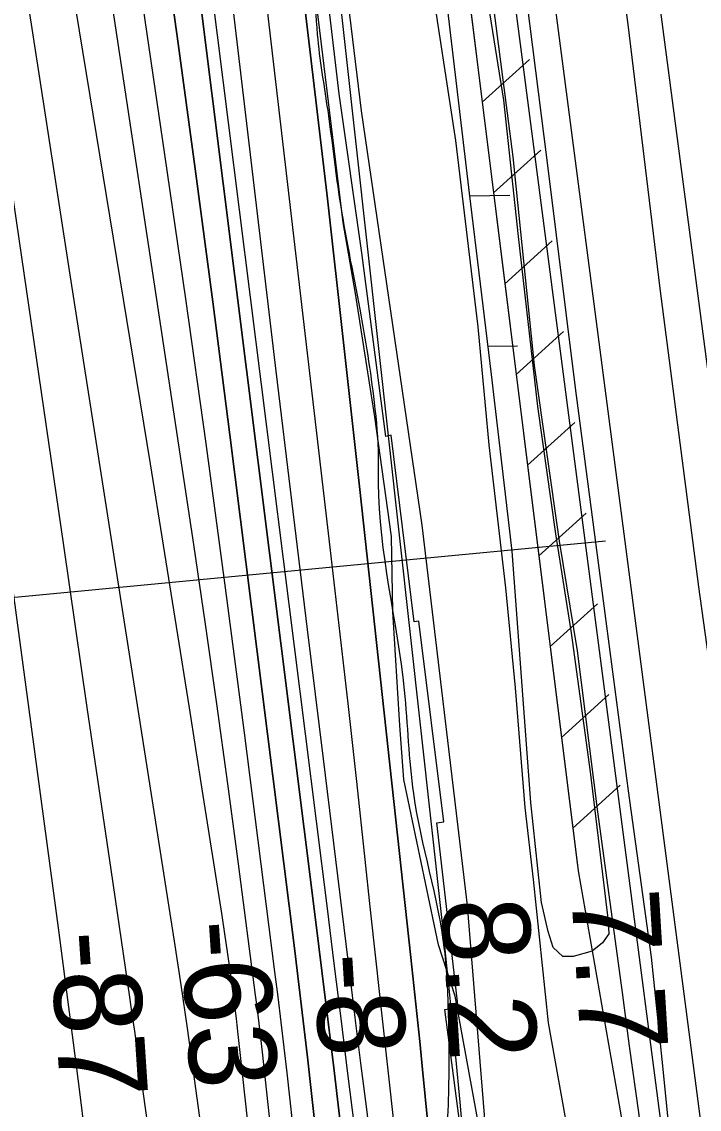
# Model space of a CAD drawing. Extents: x 3694830 to 3732949, y 415201 to 440970.
# Drawn here: x 3718315 to 3718833, y 425246 to 426079 of the extents above; entities that cross this region are included whole.
import ezdxf

# ---------------------------------------------------------------- set-up
doc = ezdxf.new("R2010")
doc.units = 0
for name, color, linetype in [('V-FLOD-BASE', 7, 'Continuous'), ('V-LEVE-TOET', 7, 'Continuous'), ('V-RIVR-EDGE', 7, 'Continuous'), ('V-RIVR-RANG', 7, 'Continuous'), ('V-ROAD-CNTR', 7, 'Continuous'), ('V-RRAP-FSHR', 7, 'Continuous'), ('V-RRAP-RVMT', 7, 'Continuous'), ('V-SITE-VEGE', 7, 'Continuous'), ('V-SURV-LINE', 7, 'Continuous'), ('V-TOPO-DPTH', 7, 'Continuous'), ('V-TOPO-MAJR', 7, 'Continuous'), ('V-TOPO-MINR', 7, 'Continuous'), ('V-TOPO-WATR', 7, 'Continuous'), ('V-WETL-SWMP', 7, 'Continuous')]:
    doc.layers.add(name, color=color, linetype=linetype)

msp = doc.modelspace()

# ---------------------------------------------------------------- linework, layer by layer
at = {"layer": 'V-FLOD-BASE'}
msp.add_lwpolyline([(3718858.85, 424393.11), (3718851.68, 424539.09), (3718851.69, 424574.68), (3718851.71, 424624.71), (3718850.69, 424666.49), (3718849.15, 424680.42), (3718844, 424708.79), (3718844, 424717.56), (3718844.52, 424728.39), (3718840.95, 424830.01), (3718832.23, 424964.64), (3718827.62, 425062.12), (3718824.03, 425114.74), (3718816.82, 425167.35), (3718805, 425284.45), (3718796.77, 425362.85), (3718779.28, 425490.26), (3718761.28, 425625.92), (3718738.64, 425798.73), (3718717.04, 425973.08), (3718690.81, 426180.44)], dxfattribs=at)
at = {"layer": 'V-LEVE-TOET'}
for points in [[(3718899.96, 425078.36), (3718901.03, 425108.14), (3718896.79, 425132.59), (3718888.31, 425204.91), (3718875.59, 425321.88), (3718855.44, 425484.58), (3718833.17, 425646.21), (3718803.47, 425874.84), (3718779.09, 426076.89), (3718752.57, 426276.81), (3718727.12, 426479.91), (3718690, 426734.07), (3718666.66, 426904.21), (3718647.58, 427073.29), (3718635.92, 427156.23), (3718626.37, 427242.37), (3718612.59, 427357.22), (3718587.13, 427524.17), (3718573.35, 427643.27)], [(3718826.56, 424506.85), (3718825.53, 424612.66), (3718820.27, 424766.31), (3718810.22, 424932.73), (3718799.13, 425134.77), (3718791.7, 425193.25), (3718787.47, 425242.17), (3718780.04, 425294.81), (3718774.74, 425335.75), (3718755.65, 425473.99), (3718740.27, 425597.34), (3718726.48, 425681.35), (3718707.39, 425815.87), (3718690.96, 425975.38), (3718667.63, 426154.56)]]:
    msp.add_lwpolyline(points, dxfattribs=at)
at = {"layer": 'V-RIVR-EDGE'}
msp.add_spline([(3716285.15, 433216.71), (3716310.38, 433178.21), (3716330.2, 433149.68), (3716351.38, 433122.49), (3716380.66, 433076.75), (3716399.14, 433050.48), (3716447.79, 432976.21), (3716475.25, 432930.47), (3716501.83, 432891.07), (3716527.51, 432851.22), (3716586.04, 432749.34), (3716608.1, 432711.75), (3716608.09, 432707.68), (3716608.07, 432700.45), (3716613.02, 432690.94), (3716627.43, 432664.23), (3716633.27, 432651.55), (3716643.19, 432639.32), (3716675.17, 432589.5), (3716706.24, 432538.33), (3716726.94, 432498.04), (3716741.33, 432463.64), (3716748.51, 432442.82), (3716788.59, 432378.52), (3716817.43, 432339.56), (3716842.2, 432297.45), (3716889.46, 432209.61), (3716920.5, 432144.42), (3716938.04, 432109.56), (3716956.5, 432075.15), (3716988.92, 432022.62), (3717009.18, 431986.85), (3717026.3, 431960.13), (3717062.32, 431897.65), (3717093.37, 431840.15), (3717112.26, 431799.86), (3717149.12, 431711.14), (3717176.54, 431644.61), (3717201.25, 431580.79), (3717210.68, 431556.35), (3717248.47, 431478.94), (3717267.81, 431435.48), (3717289.41, 431392.93), (3717306.48, 431346.77), (3717328.07, 431301.04), (3717339.31, 431276.6), (3717352.34, 431244.01), (3717362.7, 431226.35), (3717376.21, 431205.52), (3717389.26, 431178.36), (3717401.37, 431141.7), (3717407.18, 431113.2), (3717409.87, 431101.89), (3717419.75, 431075.64), (3717452.49, 430968.85), (3717469.09, 430916.81), (3717483.44, 430865.23), (3717505.45, 430810.01), (3717526.57, 430753.44), (3717540.49, 430715.43), (3717579.07, 430593.25), (3717599.25, 430526.28), (3717616.31, 430474.69), (3717628.88, 430437.13), (3717638.74, 430405), (3717647.69, 430364.28), (3717653.48, 430331.72), (3717658.42, 430314.52), (3717667.85, 430290.08), (3717679.53, 430260.66), (3717690.34, 430242.1), (3717695.71, 430221.28), (3717698.37, 430200.03), (3717697.85, 430171.99), (3717701.42, 430152.99), (3717705.91, 430140.77), (3717716.26, 430119.95), (3717727.97, 430100.48), (3717735.6, 430076.49), (3717737.82, 430059.31), (3717749.05, 430029.89), (3717760.76, 430011.77), (3717771.56, 429990.04), (3717776.48, 429968.33), (3717783.19, 429941.63), (3717791.73, 429917.65), (3717803.43, 429898.63), (3717812.42, 429876.45), (3717819.16, 429857.44), (3717834.88, 429816.71), (3717846.52, 429770.11), (3717854.12, 429734.82), (3717863.55, 429706.31), (3717878.83, 429667.39), (3717891.37, 429622.59), (3717903.49, 429586.39), (3717917.82, 429530.29), (3717931.71, 429476.45), (3717959.46, 429363.79), (3717976.51, 429307.23), (3717987.25, 429262.44), (3718014.11, 429153.85), (3718027.51, 429090.07), (3718040.47, 429028.09), (3718052.52, 428962.5), (3718057.84, 428919.98), (3718056.9, 428903.25), (3718056.86, 428887.88), (3718057.71, 428868.43), (3718061.29, 428850.79), (3718065.77, 428833.6), (3718082.36, 428779.3), (3718091.33, 428748.08), (3718100.28, 428710.98), (3718111.45, 428657.14), (3718116.36, 428631.81), (3718128.31, 428525.97), (3718136.77, 428473.05), (3718141.66, 428440.03), (3718152.32, 428360.88), (3718163.9, 428291.22), (3718171.05, 428256.38), (3718178.23, 428236.47), (3718193.92, 428178.55), (3718199.74, 428157.29), (3718197.91, 428150.06), (3718196.52, 428133.33), (3718197.39, 428121.12), (3718204.12, 428098.04), (3718215.36, 428075.41), (3718227.96, 428049.6), (3718240.08, 428011.59), (3718242.71, 427978.58), (3718251.11, 427901.24), (3718254.15, 427852.85), (3718257.69, 427822.1), (3718271.5, 427736.15), (3718281.74, 427671.92), (3718287.91, 427606.34), (3718295.91, 427551.61), (3718303.87, 427477.44), (3718310.12, 427447.13), (3718323.14, 427407.76), (3718345.15, 427350.28), (3718351.41, 427321.78), (3718363.48, 427267.49), (3718378.28, 427217.26), (3718397.99, 427141.25), (3718402.87, 427105.52), (3718405.92, 427056.68), (3718404.86, 426993.38), (3718419.58, 426915.12), (3718427.13, 426857.67), (3718428.77, 426789.85), (3718439.53, 426753.19), (3718453.89, 426709.75), (3718458.33, 426677.18), (3718461.82, 426625.18), (3718465.34, 426583.57), (3718482.71, 426479.53), (3718492.52, 426423.89), (3718501, 426378.2), (3718502.74, 426350.16), (3718512.91, 426256.09), (3718518.23, 426213.12), (3718524.03, 426182.81), (3718533.44, 426148.88), (3718540.93, 426069.28), (3718548.93, 426010.93), (3718557.81, 425944.44), (3718573.42, 425858.94), (3718584.55, 425787.48), (3718587.61, 425745.42), (3718587.56, 425725.97), (3718607.51, 425567.22), (3718614.55, 425488.07), (3718638.22, 425368.64), (3718641.26, 425318.45), (3718641.09, 425249.72), (3718640.1, 425214), (3718649.84, 425130.78), (3718658.73, 425069.26), (3718661.82, 425037.15), (3718660.41, 425016.36), (3718674.96, 424864.4), (3718675.73, 424812.85), (3718692.62, 424694.79), (3718696.05, 424618.82), (3718696.4, 424575.87), (3718706.12, 424484.51), (3718711.87, 424431.59), (3718715.41, 424403.09), (3718735.93, 424289.1), (3718746.6, 424215.37), (3718759.9, 424108.63), (3718772.36, 424027.21), (3718777.72, 423998.26), (3718795.91, 423858.04), (3718805.72, 423804.21), (3718812.44, 423776.61), (3718829, 423707.39), (3718835.67, 423662.61), (3718835.09, 423611.97), (3718835, 423576.7), (3718839.35, 423505.25), (3718842.4, 423460.03), (3718850.42, 423412.53), (3718863.4, 423357.79), (3718870.56, 423326.57), (3718873.56, 423260.55), (3718878.86, 423208.99), (3718893.63, 423148.36), (3718899, 423126.2), (3718912.45, 423080.04), (3718927.23, 423022.58), (3718930.77, 422992.73), (3718937.45, 422950.21), (3718945.92, 422900.45), (3718952.63, 422870.59), (3718968.72, 422795.95), (3718969.56, 422769.72), (3718968.13, 422738.52), (3718972.12, 422707.77), (3718981.05, 422661.17), (3718990.85, 422602.82), (3719006.89, 422506.47), (3719010.81, 422446.32), (3719014.37, 422425.06), (3719022.44, 422393.39), (3719033.2, 422359), (3719050.26, 422307.87), (3719062.77, 422249.05), (3719077.1, 422190.24), (3719087.85, 422149.06)], degree=3, dxfattribs=at)
at = {"layer": 'V-RIVR-RANG'}
msp.add_line((3718761.63, 425681.35), (3717905.5, 425599.83), dxfattribs=at)
at = {"layer": 'V-ROAD-CNTR'}
msp.add_lwpolyline([(3717815.68, 430558.65), (3717990.84, 430054.68), (3718115.31, 429687.21), (3718252.63, 429181.3), (3718402.43, 428566.28), (3718512.86, 428111.59), (3718531.2, 428036.93), (3718568.86, 427831.53), (3718621.06, 427488.45), (3718693.06, 426929.29), (3718838.59, 425820.56), (3718920.42, 425193.38), (3718947.54, 424793.91)], dxfattribs=at)
at = {"layer": 'V-RRAP-FSHR'}
for p, q in [((3718667.21, 426017.29), (3718703.42, 426050.04)), ((3718675.89, 425947.84), (3718712.1, 425980.59)), ((3718684.57, 425878.38), (3718720.79, 425911.13)), ((3718693.25, 425808.92), (3718729.47, 425841.67)), ((3718701.93, 425739.47), (3718738.15, 425772.22)), ((3718710.61, 425670.01), (3718746.83, 425702.76)), ((3718719.29, 425600.56), (3718755.51, 425633.31)), ((3718727.98, 425531.1), (3718764.19, 425563.85)), ((3718736.66, 425461.64), (3718772.87, 425494.4))]:
    msp.add_line(p, q, dxfattribs=at)
for points in [[(3717466.36, 431122.74), (3717599.65, 430720.93), (3717706.57, 430384.76), (3717801.33, 430082.96), (3717862.54, 429898.61), (3717882.46, 429834.63), (3717990.02, 429618.85), (3718021.05, 429549.34), (3718032.02, 429517.21), (3718067.52, 429247.01), (3718161.86, 428561.59), (3718206.68, 428259.33), (3718221.76, 428205.86), (3718246.87, 428158.02), (3718387.51, 427953.51), (3718417.38, 427897.22), (3718439.77, 427786.61), (3718554.49, 426909.74), (3718636.74, 426261.07), (3718740.75, 425428.94), (3718783.56, 425184.07), (3718800.84, 424873.2)], [(3718391.12, 427348.28), (3718475.54, 426733.12), (3718537.58, 426315.32), (3718574.68, 426010.61), (3718621.14, 425693.56), (3718655.82, 425402.36), (3718689.05, 424990.86), (3718733.51, 424580.69), (3718746.96, 424380.12), (3718784.4, 424103.55), (3718845.23, 423695.11), (3718886.06, 423421.61), (3718923.4, 423190.48), (3718957.44, 423026.17), (3718988.34, 422871.6), (3719013.63, 422718.01), (3719111.7, 422210.46), (3719157.05, 422005.7), (3719219.83, 421828.02), (3719374.72, 421477.77), (3719529.57, 421100.78)], [(3718633.06, 426290.02), (3718636.74, 426261.07), (3718740.28, 425432.66)]]:
    msp.add_lwpolyline(points, dxfattribs=at)
at = {"layer": 'V-RRAP-RVMT'}
for p, q in [((3718557.76, 426023.86), (3718522.57, 426319.79)), ((3718575.17, 425901.98), (3718557.76, 426023.86)), ((3718593.34, 425761.39), (3718575.17, 425901.98)), ((3718597.66, 425762.31), (3718593.34, 425761.39)), ((3718615.26, 425619.44), (3718597.66, 425762.31)), ((3718618.79, 425619.93), (3718615.26, 425619.44)), ((3718637.92, 425466.48), (3718618.79, 425619.93)), ((3718632.59, 425465.68), (3718637.92, 425466.48)), ((3718648.83, 425324.3), (3718632.59, 425465.68)), ((3718638.59, 425322.71), (3718648.83, 425324.3)), ((3718657, 425184.58), (3718638.59, 425322.71))]:
    msp.add_line(p, q, dxfattribs=at)
at = {"layer": 'V-SITE-VEGE'}
for points in [[(3718560.66, 425925.24), (3718540.52, 426091.13), (3718519.29, 426204.92), (3718500.18, 426294.25), (3718476.83, 426406.97), (3718461.97, 426480.35), (3718453.49, 426585.62), (3718447.17, 426729.18), (3718436.57, 426844.03), (3718419.6, 426964.19), (3718404.75, 427063.09), (3718392.02, 427149.23), (3718384.6, 427217.28), (3718363.37, 427322.56)], [(3718626.66, 426119.81), (3718646.82, 425987.95), (3718663.78, 425845.45), (3718672.26, 425755.07), (3718684.98, 425645.53), (3718692.39, 425568.97), (3718699.81, 425477.52), (3718706.17, 425422.22), (3718717.82, 425312.69), (3718730.56, 425241.44), (3718742.24, 425178.7), (3718752.84, 425107.45), (3718777.25, 424946.88), (3718786.77, 424811.83), (3718794.18, 424737.39), (3718798.4, 424611.91), (3718807.89, 424386.48)], [(3718732.43, 424497.09), (3718714.43, 424710.83), (3718682.62, 424987.32), (3718680.52, 425067.07), (3718675.24, 425176.6), (3718646.59, 425332.92), (3718633.84, 425372.27), (3718607.3, 425498.82), (3718604.13, 425540.29), (3718598.84, 425627.49), (3718597.79, 425684.91), (3718585.07, 425776.36), (3718570.21, 425871.01), (3718560.66, 425925.24)]]:
    msp.add_lwpolyline(points, dxfattribs=at)
at = {"layer": 'V-SURV-LINE'}
for points in [[(3718634.41, 426770.9), (3718856.78, 425064.78)], [(3718827.03, 425060.9), (3718604.66, 426767.03)]]:
    msp.add_lwpolyline(points, dxfattribs=at)
at = {"layer": 'V-TOPO-DPTH'}
for points in [[(3718670.31, 424483.88), (3718583.05, 425211.38), (3718580.93, 425228.93), (3718578.79, 425246.49), (3718576.62, 425264.04), (3718574.43, 425281.59), (3718570.58, 425312.31), (3718570.31, 425314.49), (3718570.03, 425316.68), (3718569.76, 425318.87), (3718569.49, 425321.05), (3718545.66, 425514.59), (3718533.54, 425613.55), (3718521.51, 425712.53), (3718509.61, 425811.52), (3718497.81, 425910.52), (3718443.62, 426367.62)], [(3718670.31, 424483.88), (3718583.05, 425211.38), (3718580.93, 425228.93), (3718578.79, 425246.49), (3718576.62, 425264.04), (3718574.43, 425281.59), (3718570.58, 425312.31), (3718570.31, 425314.49), (3718570.03, 425316.68), (3718569.76, 425318.87), (3718569.49, 425321.05), (3718545.66, 425514.59), (3718533.54, 425613.55), (3718521.51, 425712.53), (3718509.61, 425811.52), (3718497.81, 425910.52), (3718443.62, 426367.62)], [(3718607, 424453.09), (3718593.5, 424579.9), (3718585.63, 424653.5), (3718577.71, 424727.09), (3718569.72, 424800.68), (3718561.68, 424874.26), (3718517.79, 425274.31), (3718515.61, 425293.68), (3718513.36, 425313.04), (3718511.01, 425332.39), (3718508.59, 425351.73), (3718485.17, 425534.67), (3718470.69, 425645.44), (3718455.79, 425756.15), (3718440.29, 425866.77), (3718424.37, 425977.34), (3718371.67, 426336.47)], [(3718607, 424453.09), (3718593.5, 424579.9), (3718585.63, 424653.5), (3718577.71, 424727.09), (3718569.72, 424800.68), (3718561.68, 424874.26), (3718517.79, 425274.31), (3718515.61, 425293.68), (3718513.36, 425313.04), (3718511.01, 425332.39), (3718508.59, 425351.73), (3718485.17, 425534.67), (3718470.69, 425645.44), (3718455.79, 425756.15), (3718440.29, 425866.77), (3718424.37, 425977.34), (3718371.67, 426336.47)], [(3718419.47, 426169.6), (3718433.69, 426067.94), (3718447.58, 425966.24), (3718460.98, 425864.48), (3718474.04, 425762.67), (3718523.47, 425369.65), (3718526.9, 425341.89), (3718530.25, 425314.12), (3718533.47, 425286.34), (3718536.61, 425258.54), (3718623.34, 424474.84)], [(3718419.47, 426169.6), (3718433.69, 426067.94), (3718447.58, 425966.24), (3718460.98, 425864.48), (3718474.04, 425762.67), (3718523.47, 425369.65), (3718526.9, 425341.89), (3718530.25, 425314.12), (3718533.47, 425286.34), (3718536.61, 425258.54), (3718623.34, 424474.84)], [(3718522.76, 426163.4), (3718535.84, 426053.4), (3718548.67, 425943.38), (3718561.13, 425833.31), (3718573.34, 425723.22), (3718612.71, 425362.49), (3718615.01, 425341.1), (3718617.26, 425319.7), (3718619.45, 425298.29), (3718621.58, 425276.88), (3718655.35, 424933.08), (3718663.54, 424850.9), (3718671.89, 424768.74), (3718680.49, 424686.61), (3718689.25, 424604.49), (3718704.6, 424462.53)], [(3718451.25, 426095.4), (3718539.91, 425389.51), (3718544.53, 425352.42), (3718549.09, 425315.33), (3718553.56, 425278.22), (3718557.99, 425241.11), (3718578.09, 425070.72), (3718590.5, 424964.95), (3718602.8, 424859.17), (3718614.96, 424753.37), (3718627.02, 424647.57), (3718648.58, 424457.23)], [(3718648.58, 424457.23), (3718627.02, 424647.57), (3718614.96, 424753.37), (3718602.8, 424859.17), (3718590.5, 424964.95), (3718578.09, 425070.72), (3718557.99, 425241.11), (3718553.56, 425278.22), (3718549.09, 425315.33), (3718544.53, 425352.42), (3718539.91, 425389.51), (3718451.25, 426095.4)]]:
    msp.add_lwpolyline(points, dxfattribs=at)
at = {"layer": 'V-TOPO-MAJR'}
msp.add_lwpolyline([(3718586.47, 424470.19), (3718549.39, 424821.88), (3718540.74, 424903.58), (3718532.03, 424985.27), (3718523.24, 425066.96), (3718514.39, 425148.63), (3718499, 425290.07), (3718497.78, 425301.02), (3718496.51, 425311.96), (3718495.16, 425322.9), (3718493.78, 425333.83), (3718480.7, 425434.36), (3718472.56, 425495.52), (3718464.16, 425556.64), (3718455.39, 425617.72), (3718446.37, 425678.76), (3718343.83, 426358.25)], dxfattribs=at)
at = {"layer": 'V-TOPO-MINR'}
for points in [[(3718670.31, 424483.88), (3718583.05, 425211.38), (3718580.93, 425228.93), (3718578.79, 425246.49), (3718576.62, 425264.04), (3718574.43, 425281.59), (3718570.58, 425312.31), (3718570.31, 425314.49), (3718570.03, 425316.68), (3718569.76, 425318.87), (3718569.49, 425321.05), (3718545.66, 425514.59), (3718533.54, 425613.55), (3718521.51, 425712.53), (3718509.61, 425811.52), (3718497.81, 425910.52), (3718443.62, 426367.62)], [(3718509.4, 424528.84), (3718505.26, 424563.13), (3718500.81, 424597.38), (3718496.15, 424631.61), (3718404.88, 425279.9), (3718403.02, 425292.98), (3718401.16, 425306.06), (3718399.27, 425319.14), (3718397.36, 425332.21), (3718383.04, 425430.03), (3718373.96, 425492.01), (3718364.9, 425553.99), (3718355.86, 425615.97), (3718346.82, 425677.96), (3718249.78, 426344.05)], [(3718683.98, 424500.26), (3718632.02, 424949.12), (3718624.95, 425010.58), (3718617.94, 425072.05), (3718611.02, 425133.53), (3718604.16, 425195.01), (3718599.77, 425234.65), (3718595.17, 425276.32), (3718590.6, 425318), (3718586.07, 425359.68), (3718581.56, 425401.37), (3718577.67, 425437.53), (3718571.15, 425497.29), (3718564.53, 425557.04), (3718557.75, 425616.77), (3718550.87, 425676.49), (3718473, 426343.95)], [(3718607, 424453.09), (3718593.5, 424579.9), (3718585.63, 424653.5), (3718577.71, 424727.09), (3718569.72, 424800.68), (3718561.68, 424874.26), (3718517.79, 425274.31), (3718515.61, 425293.68), (3718513.36, 425313.04), (3718511.01, 425332.39), (3718508.59, 425351.73), (3718485.17, 425534.67), (3718470.69, 425645.44), (3718455.79, 425756.15), (3718440.29, 425866.77), (3718424.37, 425977.34), (3718371.67, 426336.47)], [(3718714.19, 424528.36), (3718712.17, 424550.09), (3718710.21, 424571.82), (3718650.36, 425251.76), (3718647.17, 425286.58), (3718643.84, 425321.39), (3718640.26, 425356.17), (3718636.54, 425390.94), (3718538.4, 426278.34)], [(3718659.02, 424469.97), (3718605.23, 424933.54), (3718597.77, 424997.31), (3718590.24, 425061.06), (3718582.59, 425124.8), (3718574.87, 425188.54), (3718569.6, 425231.76), (3718564.43, 425273.87), (3718559.24, 425315.98), (3718553.99, 425358.09), (3718548.72, 425400.19), (3718439.35, 426269.59)], [(3718623.34, 424474.84), (3718536.61, 425258.54), (3718533.47, 425286.34), (3718530.25, 425314.12), (3718526.9, 425341.89), (3718523.47, 425369.65), (3718474.04, 425762.67), (3718460.98, 425864.48), (3718447.58, 425966.24), (3718433.69, 426067.94), (3718419.47, 426169.6)], [(3718548.74, 424449.35), (3718527.48, 424636.08), (3718515.35, 424739.99), (3718502.83, 424843.85), (3718489.71, 424947.64), (3718476.2, 425051.37), (3718450.84, 425241.89), (3718446.28, 425275.21), (3718441.58, 425308.51), (3718436.64, 425341.78), (3718431.56, 425375.02), (3718388.98, 425646.97), (3718370.37, 425766.06), (3718351.83, 425885.17), (3718333.36, 426004.28), (3718314.95, 426123.41)], [(3718565.98, 424487.3), (3718491.62, 425199.3), (3718489.66, 425217.91), (3718487.7, 425236.51), (3718485.71, 425255.11), (3718483.72, 425273.7), (3718480.25, 425305.84), (3718479.97, 425308.37), (3718479.68, 425310.89), (3718479.37, 425313.42), (3718479.05, 425315.94), (3718476.04, 425338.88), (3718474.16, 425352.86), (3718472.21, 425366.84), (3718470.15, 425380.8), (3718468.03, 425394.75), (3718452.96, 425491.44), (3718443.18, 425553.71), (3718433.3, 425615.97), (3718423.29, 425678.21), (3718413.18, 425740.43), (3718353.78, 426103.41)], [(3718648.58, 424457.23), (3718627.02, 424647.57), (3718614.96, 424753.37), (3718602.8, 424859.17), (3718590.5, 424964.95), (3718578.09, 425070.72), (3718557.99, 425241.11), (3718553.56, 425278.22), (3718549.09, 425315.33), (3718544.53, 425352.42), (3718539.91, 425389.51), (3718451.25, 426095.4)], [(3718449.13, 424441.47), (3718415.12, 424773.2), (3718405.8, 424861.61), (3718396.14, 424949.98), (3718385.96, 425038.29), (3718375.45, 425126.56), (3718363.48, 425224.59), (3718358.62, 425263.81), (3718353.66, 425303.02), (3718348.56, 425342.21), (3718343.36, 425381.39), (3718256.58, 426025.57), (3718249.12, 426080.49)]]:
    msp.add_lwpolyline(points, dxfattribs=at)
at = {"layer": 'V-TOPO-WATR'}
msp.add_lwpolyline([(3718704.6, 424462.53), (3718689.25, 424604.49), (3718680.49, 424686.61), (3718671.89, 424768.74), (3718663.54, 424850.9), (3718655.35, 424933.08), (3718621.58, 425276.88), (3718619.45, 425298.29), (3718617.26, 425319.7), (3718615.01, 425341.1), (3718612.71, 425362.49), (3718573.34, 425723.22), (3718561.13, 425833.31), (3718548.67, 425943.38), (3718535.84, 426053.4), (3718522.76, 426163.4)], dxfattribs=at)
at = {"layer": 'V-WETL-SWMP'}
for p, q in [((3718657.65, 425945.75), (3718688.37, 425946.11)), ((3718671.75, 425830.48), (3718694.35, 425830.74))]:
    msp.add_line(p, q, dxfattribs=at)
msp.add_lwpolyline([(3718671.84, 426092.18), (3718683.51, 426018.81), (3718694.64, 425914.6), (3718709.48, 425784.33), (3718723.27, 425687.03), (3718735.47, 425611), (3718749.79, 425504.66), (3718763.57, 425390.35), (3718764.1, 425380.77), (3718759.31, 425373.86), (3718751.33, 425367.49), (3718736.98, 425363.24), (3718729, 425363.24), (3718721.56, 425370.16), (3718717.84, 425382.39), (3718712.53, 425404.72), (3718709.89, 425430.77), (3718704.59, 425481.28), (3718690.3, 425673.75), (3718674.4, 425808.8), (3718657.43, 425947.57), (3718640.47, 426092.2)], dxfattribs=at)

# ---------------------------------------------------------------- texts
at = {"layer": 'V-RIVR-RANG'}
for s, rotation, p in [('7.7', 273.51833, (3718735.34, 425412.99)), ('8.2', 273.51833, (3718635.54, 425406.6)), ('-63', 273.80575, (3718435.8, 425389.67)), ('-87', 273.80575, (3718336.12, 425381.45)), ('-8', 273.51833, (3718537.93, 425364.66))]:
    msp.add_text(s, height=67, rotation=rotation, dxfattribs=at).set_placement(p)

doc.saveas('drawing.dxf')
